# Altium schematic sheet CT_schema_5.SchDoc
size 254 x 245 mm
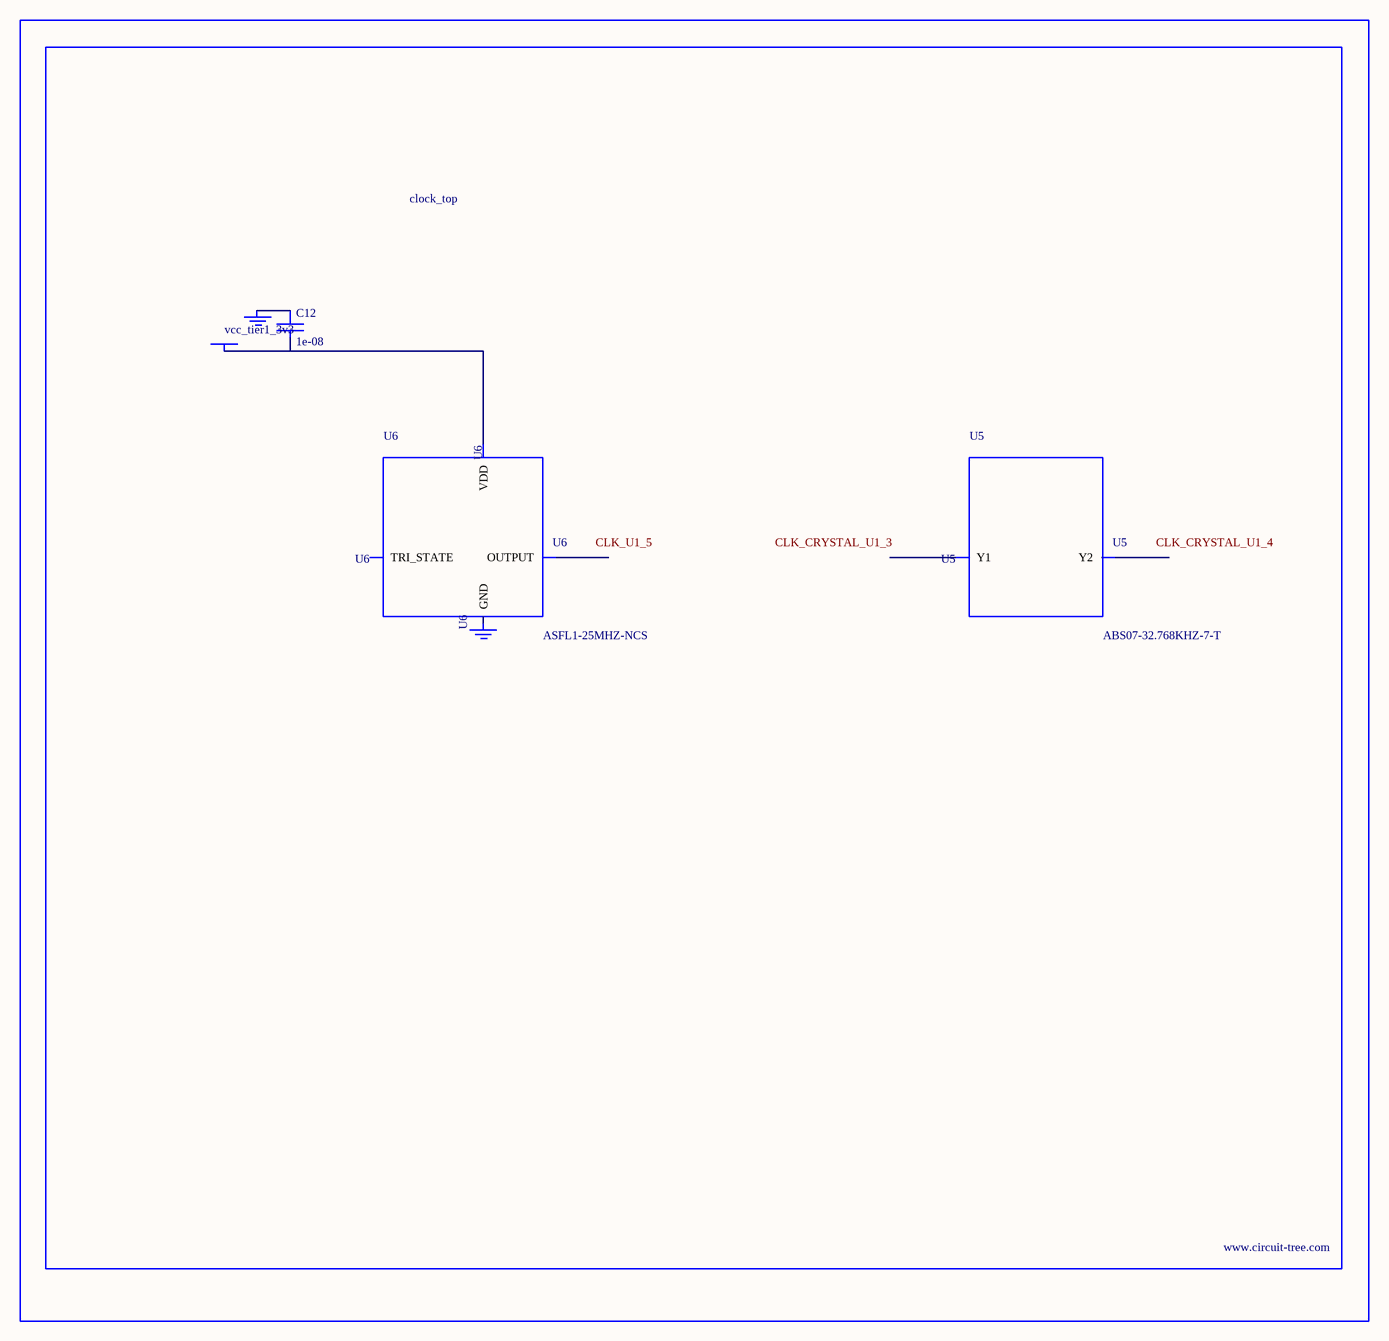
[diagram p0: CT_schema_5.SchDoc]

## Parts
BORDER4  (no value)
C12  1e-08  [C0402]
GND_INSTANCE_4_0  (no value)
GND_INSTANCE_4_1  (no value)
POWER_INSTANCE_4_0  vcc_tier1_3v3
U5  ABS07-32.768KHZ-7-T  [ABS07-32.768KHZ-7-T]
U6  ASFL1-25MHZ-NCS  [ASFL1]

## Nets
NetC12_1: C12.1 GND_INSTANCE_4_0.0(GND)
NetC12_2: C12.2 POWER_INSTANCE_4_0.0(PWR) U6.4(VDD)

Not connected (* = marked no-connect by the designer): GND_INSTANCE_4_1 0(GND); U5 1(Y1) 2(Y2); U6 1(TRI_STATE) 2(GND) 3(OUTPUT)

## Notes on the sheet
- Labels drawn without touching a wire or pin: CLK_CRYSTAL_U1_3, CLK_CRYSTAL_U1_4, CLK_U1_5

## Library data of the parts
BORDER4 = BORDER_PAGE4
C12 = C0402C103K3RAC
GND_INSTANCE_4_0 GND_INSTANCE_4_1 = GND
POWER_INSTANCE_4_0 = PWR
